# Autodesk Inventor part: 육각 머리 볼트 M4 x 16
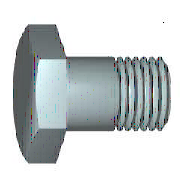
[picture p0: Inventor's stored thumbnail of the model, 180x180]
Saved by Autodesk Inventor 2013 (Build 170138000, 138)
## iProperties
IsCustomPart: 0
Created: 2012-02
Part Number: 육각 머리 볼트 M4 x 16
Material: 강철, 연강
Description: 6각 머리 볼트 및 6각 머리 나사
Document SubType Name: Modeling
Standard: KS B 1002
Designer: mduedu
Standards Organization: KS
Language: ko-KR
Size Designation: A + B M4 x 16
Categories: <MemberInstance><Categories><Category DisplayName="조임쇠" InternalName="e4da775c-781d-43d5-af7c-5136215cf5a6" Mnemonic="FSTN"><Category DisplayName="볼트" InternalN
Density: 1 g/cm^3
Author: mduedu
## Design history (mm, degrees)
sketch "스케치1"
  geometry: L1 (0, 2.94)-(0, 2); L2 (2.1, 2)-(16, 2); L3 (16, 2)-(16, 0); L4 (16, 0)-(-0.4, 0); L5 (-3.68, 0)-(19.28, 0) reference; L6 (-0.4, 0)-(-0.4, 2.94); L7 (-0.4, 2.94)-(0, 2.94); L8 (2.1, 2)-(1.67, 2); L9 (1.67, 2)-(0, 2); L10 (0, -0.588)-(0, 3.528) reference
  constraints: 16 end point, 2 collinear, 2 perpendicular, 1 parallel
  dimensions: "d0" = 16 distance between parallel lines of L3 L1 (= NLG); "d1" = 13.9 distance from line of L2.start L3 (= GEL); "d2" = 4 diameter of L2 L4 (= GD); "d9" = 0.4001 distance between parallel lines of L6 L1 (computed from SD); "d10" = 5.88 diameter of L7 L4 (= SD2); "d13" = 0.42952 distance of L2.start L8.end (computed from GAL); "d14" = 4 diameter of L9 L4 (= BDM)
revolve "본체" sketch "스케치1" stored, may be unused: angle "d12" = 90 deg
sketch "스케치2"
  geometry: L1 (0, 4.041)-(3.5, 2.021); L2 (3.5, 2.021)-(3.5, -2.021); L3 (3.5, -2.021)-(0, -4.041); L4 (0, -4.041)-(-3.5, -2.021); L5 (-3.5, -2.021)-(-3.5, 2.021); L6 (-3.5, 2.021)-(0, 4.041); 2 further points
  constraints: 12 end point, 1 coincident, 1 vertical, 11 other
  dimensions: "d11" = 7 distance between parallel lines of L5 L2 (= SW)
extrude "머리" join sketch "스케치2" distance "d3" = 2.4 (= KOH - SD); taper "d4" = 0 deg
sketch "스케치4"
  geometry: L1 (-2.8, 3.5)-(-2.8, 4.041); L2 (-2.8, 4.041)-(-2.487, 4.041); L3 (-2.487, 4.041)-(-2.8, 3.5); L4 (-3.28, 0)-(0.08, 0) reference; L5 (-0.4, 4.041)-(-2.8, 4.041) reference; L6 (-2.8, 2.021)-(-2.8, 4.041) reference
  constraints: 6 end point, 2 collinear, 1 perpendicular, 1 vertical
  dimensions: "d5" = 30 deg angle of L3 L1 (= ANG1); "d19" = 7 diameter of L1.start L4 (= SW0)
revolve "모따기1" sketch "스케치4" stored, may be unused: angle "d21" = 90 deg
workplane "Work Plane1"
body "Solid1"
feature "스레드" dims "d15" = 13.9 (= GEL), "d16" = 0
chamfer "모따기2" distance "d6" = 0.42941 (= -0.5 x SPD + 0.5 x GD); stored, may be unused: second distance "d7" = 0.42952 (computed from GUL), angle "d55" = 45 deg
other parameters: "NLG" = 16 [user parameter; used in 1 equation term], "GD" = 4 (= NND) [user parameter; used in 2 equation terms], "BDM" = 4 (= NND) [user parameter; used in 1 equation term], "KOH" = 2.8 [user parameter; used in 1 equation term], "GEL" = 13.9 [user parameter; used in 2 equation terms], "SW" = 7 [user parameter; used in 3 equation terms], "SW0" = 7 (= SW) [user parameter; used in 1 equation term], "SPD" = 3.14117 (= NND - 1.2269 x PTC) [user parameter; used in 1 equation term], "SD2" = 5.88 (= SDH) [user parameter; used in 1 equation term], "SD" = 0.4 [user parameter; used in 2 equation terms], "ANG1" = 30 deg [user parameter; used in 1 equation term], "GAL" = 0.42941 (= 0.61345 x PTC) [user parameter; used in 1 equation term], "GUL" = 0.42941 (= 0.61345 x PTC) [user parameter; used in 1 equation term], "d8" = 0, "RR" = 0.2 [user parameter], "d57" = 0, "d58" = 0, "TPU" = 14.28571 (computed from PTC) [user parameter], "GD1" = 3.14117 (= THREADDIA - 1.2269 x PTC) [user parameter], "THREADDIA" = 4 [user parameter; used in 1 equation term], "SDH" = 5.88 [user parameter; used in 1 equation term], "SDHG" = 2.1 [user parameter], "TOA" = 30 deg [user parameter], "PTC" = 0.7 [user parameter; used in 5 equation terms], "NND" = 4 [user parameter; used in 3 equation terms], "E0" = 8.085 (= 1.155 x SW) [user parameter]
